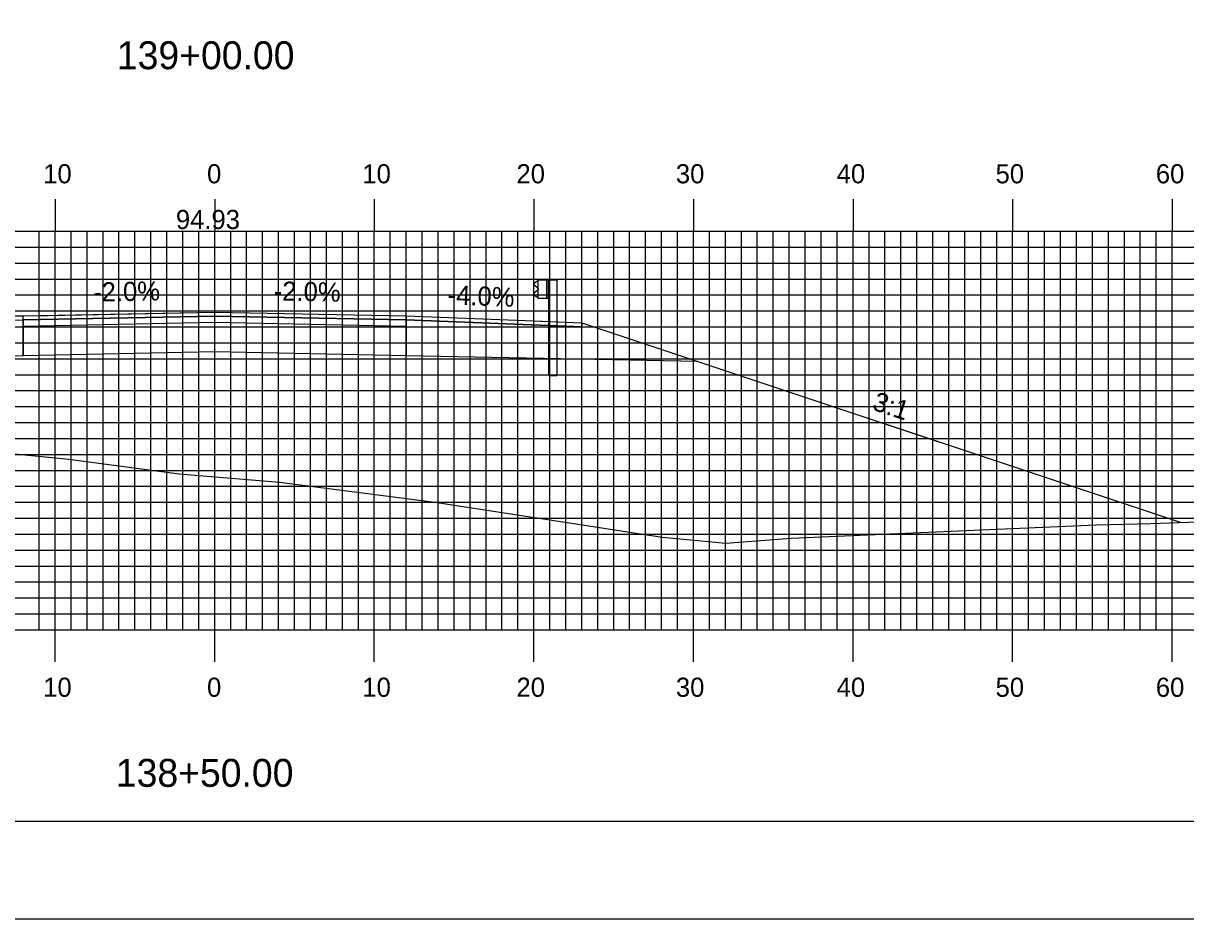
# Model space of a CAD drawing. Extents: x 1775957 to 1776301, y 442591 to 442811.
# Drawn here: x 1776111.2 to 1776184.1, y 442590.5 to 442646.7 of the extents above; entities that cross this region are included whole.
import ezdxf

# ---------------------------------------------------------------- set-up
doc = ezdxf.new("R2010")
doc.units = 0
for name, color, linetype in [('ANNOTATION', 7, 'Continuous'), ('BORDER', 7, 'Continuous'), ('D_Guardrail_Beam_Rt', 7, 'Continuous'), ('D_Roadway_Centerline', 7, 'Continuous'), ('D_Roadway_Centerline_Text', 7, 'Continuous'), ('D_Roadway_Edge_Shoulder', 7, 'Continuous'), ('D_Roadway_Edge_TW', 7, 'Continuous'), ('D_Roadway_Pavement', 7, 'Continuous'), ('D_Roadway_SlopeLines', 7, 'Continuous'), ('D_Roadway_SubGrade', 7, 'Continuous'), ('H_V ANNOTATION', 7, 'Continuous'), ('MAJOR', 7, 'Continuous'), ('MINOR', 7, 'Continuous'), ('PLOT BOUNDARY', 7, 'Continuous'), ('S_Roadway_Centerline', 7, 'Continuous')]:
    doc.layers.add(name, color=color, linetype=linetype)

msp = doc.modelspace()

# ---------------------------------------------------------------- linework, layer by layer
at = {"layer": 'BORDER'}
msp.add_lwpolyline([(1775973.624, 442596.665), (1776293.624, 442596.665), (1776293.624, 442806.665), (1775973.624, 442806.665)], close=True, dxfattribs=at)
at = {"layer": 'D_Guardrail_Beam_Rt'}
for p, q in [((1776143.405, 442630.513), (1776143.262, 442630.413)), ((1776143.495, 442630.534), (1776143.421, 442630.52)), ((1776143.495, 442630.618), (1776144.183, 442630.618)), ((1776143.495, 442629.451), (1776143.495, 442630.618)), ((1776144.016, 442630.618), (1776144.016, 442629.451)), ((1776144.12, 442630.618), (1776144.12, 442629.451)), ((1776144.183, 442630.618), (1776144.653, 442630.618)), ((1776144.183, 442630.618), (1776144.183, 442629.451)), ((1776144.653, 442630.618), (1776144.653, 442624.618)), ((1776143.262, 442630.27), (1776143.457, 442630.134)), ((1776143.457, 442629.935), (1776143.262, 442629.799)), ((1776143.491, 442630.069), (1776143.491, 442629.999)), ((1776143.262, 442629.655), (1776143.405, 442629.555)), ((1776143.421, 442629.549), (1776143.495, 442629.534)), ((1776144.183, 442629.451), (1776143.495, 442629.451)), ((1776144.162, 442624.618), (1776144.162, 442629.451)), ((1776144.162, 442624.618), (1776144.653, 442624.618))]:
    msp.add_line(p, q, dxfattribs=at)
for centre, major_axis, start_param, end_param in [((1776143.429, 442630.479), (-0.0417, 0), 4.907132, 5.323254), ((1776143.312, 442630.341), (-0.0877, 0), 5.323254, 7.243116), ((1776143.312, 442629.727), (-0.0877, 0), 5.323254, 7.243116), ((1776143.412, 442630.069), (0.0789, 0), 0, 0.959931), ((1776143.412, 442629.999), (0.0789, 0), 5.323254, 6.283185), ((1776143.429, 442629.589), (-0.0417, 0), 0.959931, 1.376053)]:
    msp.add_ellipse(centre, major_axis=major_axis, ratio=0.995501, start_param=start_param, end_param=end_param, dxfattribs=at)
at = {"layer": 'D_Roadway_Centerline'}
msp.add_lwpolyline([(1776076.998, 442623.12), (1776081.579, 442624.647), (1776081.581, 442624.648), (1776083.119, 442625.033), (1776084.245, 442625.314), (1776084.249, 442625.315), (1776093.581, 442627.648), (1776093.59, 442627.649), (1776111.225, 442628.354), (1776112.792, 442628.386), (1776123.225, 442628.594), (1776135.224, 442628.354), (1776143.224, 442628.034), (1776144.123, 442627.998), (1776146.224, 442627.914), (1776153.5, 442625.489), (1776153.501, 442625.488), (1776183.777, 442615.396)], dxfattribs=at)
at = {"layer": 'D_Roadway_Edge_Shoulder'}
for points in [[(1776111.225, 442628.354), (1776093.581, 442627.648), (1776093.581, 442627.398), (1776111.225, 442628.104)], [(1776135.224, 442628.354), (1776143.224, 442628.034), (1776143.224, 442628.034), (1776146.224, 442627.914), (1776146.224, 442627.664), (1776135.224, 442628.104)]]:
    msp.add_lwpolyline(points, close=True, dxfattribs=at)
at = {"layer": 'D_Roadway_Edge_TW'}
msp.add_lwpolyline([(1776111.225, 442628.104), (1776111.225, 442628.354), (1776123.225, 442628.594), (1776135.224, 442628.354), (1776135.224, 442628.104), (1776123.225, 442628.344)], close=True, dxfattribs=at)
at = {"layer": 'D_Roadway_Pavement'}
msp.add_lwpolyline([(1776111.225, 442627.687), (1776111.225, 442628.104), (1776123.225, 442628.344), (1776135.224, 442628.104), (1776135.224, 442627.687), (1776123.225, 442627.927)], close=True, dxfattribs=at)
at = {"layer": 'D_Roadway_SlopeLines'}
msp.add_lwpolyline([(1776146.224, 442627.914), (1776183.777, 442615.396)], dxfattribs=at)
at = {"layer": 'D_Roadway_SubGrade'}
for points in [[(1776111.225, 442625.854), (1776111.225, 442628.104), (1776123.225, 442628.344), (1776135.224, 442628.104), (1776135.224, 442625.854), (1776123.225, 442626.094)], [(1776111.225, 442625.854), (1776084.245, 442625.314), (1776093.581, 442627.648), (1776093.581, 442627.398), (1776111.225, 442628.104)], [(1776135.224, 442628.104), (1776146.224, 442627.664), (1776146.224, 442627.914), (1776153.501, 442625.488), (1776135.224, 442625.854)]]:
    msp.add_lwpolyline(points, close=True, dxfattribs=at)
at = {"layer": 'MAJOR'}
for p, q in [((1776113.224, 442635.669), (1776113.224, 442633.665)), ((1776123.224, 442635.669), (1776123.224, 442633.665)), ((1776133.224, 442635.669), (1776133.224, 442633.665)), ((1776143.224, 442635.669), (1776143.224, 442633.665)), ((1776153.224, 442635.669), (1776153.224, 442633.665)), ((1776163.224, 442635.669), (1776163.224, 442633.665)), ((1776173.224, 442635.669), (1776173.224, 442633.665)), ((1776183.224, 442635.669), (1776183.224, 442633.665)), ((1775983.224, 442633.665), (1776263.224, 442633.665)), ((1775983.224, 442633.665), (1776263.224, 442633.665)), ((1776113.224, 442608.665), (1776113.224, 442633.665)), ((1776123.224, 442608.665), (1776123.224, 442633.665)), ((1776133.224, 442608.665), (1776133.224, 442633.665)), ((1776143.224, 442608.665), (1776143.224, 442633.665)), ((1776153.224, 442608.665), (1776153.224, 442633.665)), ((1776163.224, 442608.665), (1776163.224, 442633.665)), ((1776173.224, 442608.665), (1776173.224, 442633.665)), ((1776183.224, 442608.665), (1776183.224, 442633.665)), ((1775983.224, 442628.665), (1776263.224, 442628.665)), ((1775983.224, 442623.665), (1776263.224, 442623.665)), ((1775983.224, 442618.665), (1776263.224, 442618.665)), ((1775983.224, 442613.665), (1776263.224, 442613.665)), ((1775983.224, 442608.665), (1776263.224, 442608.665)), ((1775983.224, 442608.665), (1776263.224, 442608.665)), ((1776113.224, 442606.661), (1776113.224, 442608.665)), ((1776123.224, 442606.661), (1776123.224, 442608.665)), ((1776133.224, 442606.661), (1776133.224, 442608.665)), ((1776143.224, 442606.661), (1776143.224, 442608.665)), ((1776153.224, 442606.661), (1776153.224, 442608.665)), ((1776163.224, 442606.661), (1776163.224, 442608.665)), ((1776173.224, 442606.661), (1776173.224, 442608.665)), ((1776183.224, 442606.661), (1776183.224, 442608.665))]:
    msp.add_line(p, q, dxfattribs=at)
at = {"layer": 'MINOR'}
for p, q in [((1776112.224, 442608.665), (1776112.224, 442633.665)), ((1776114.224, 442608.665), (1776114.224, 442633.665)), ((1776115.224, 442608.665), (1776115.224, 442633.665)), ((1776116.224, 442608.665), (1776116.224, 442633.665)), ((1776117.224, 442608.665), (1776117.224, 442633.665)), ((1776118.224, 442608.665), (1776118.224, 442633.665)), ((1776119.224, 442608.665), (1776119.224, 442633.665)), ((1776120.224, 442608.665), (1776120.224, 442633.665)), ((1776121.224, 442608.665), (1776121.224, 442633.665)), ((1776122.224, 442608.665), (1776122.224, 442633.665)), ((1776124.224, 442608.665), (1776124.224, 442633.665)), ((1776125.224, 442608.665), (1776125.224, 442633.665)), ((1776126.224, 442608.665), (1776126.224, 442633.665)), ((1776127.224, 442608.665), (1776127.224, 442633.665)), ((1776128.224, 442608.665), (1776128.224, 442633.665)), ((1776129.224, 442608.665), (1776129.224, 442633.665)), ((1776130.224, 442608.665), (1776130.224, 442633.665)), ((1776131.224, 442608.665), (1776131.224, 442633.665)), ((1776132.224, 442608.665), (1776132.224, 442633.665)), ((1776134.224, 442608.665), (1776134.224, 442633.665)), ((1776135.224, 442608.665), (1776135.224, 442633.665)), ((1776136.224, 442608.665), (1776136.224, 442633.665)), ((1776137.224, 442608.665), (1776137.224, 442633.665)), ((1776138.224, 442608.665), (1776138.224, 442633.665)), ((1776139.224, 442608.665), (1776139.224, 442633.665)), ((1776140.224, 442608.665), (1776140.224, 442633.665)), ((1776141.224, 442608.665), (1776141.224, 442633.665)), ((1776142.224, 442608.665), (1776142.224, 442633.665)), ((1776144.224, 442608.665), (1776144.224, 442633.665)), ((1776145.224, 442608.665), (1776145.224, 442633.665)), ((1776146.224, 442608.665), (1776146.224, 442633.665)), ((1776147.224, 442608.665), (1776147.224, 442633.665)), ((1776148.224, 442608.665), (1776148.224, 442633.665)), ((1776149.224, 442608.665), (1776149.224, 442633.665)), ((1776150.224, 442608.665), (1776150.224, 442633.665)), ((1776151.224, 442608.665), (1776151.224, 442633.665)), ((1776152.224, 442608.665), (1776152.224, 442633.665)), ((1776154.224, 442608.665), (1776154.224, 442633.665)), ((1776155.224, 442608.665), (1776155.224, 442633.665)), ((1776156.224, 442608.665), (1776156.224, 442633.665)), ((1776157.224, 442608.665), (1776157.224, 442633.665)), ((1776158.224, 442608.665), (1776158.224, 442633.665)), ((1776159.224, 442608.665), (1776159.224, 442633.665)), ((1776160.224, 442608.665), (1776160.224, 442633.665)), ((1776161.224, 442608.665), (1776161.224, 442633.665)), ((1776162.224, 442608.665), (1776162.224, 442633.665)), ((1776164.224, 442608.665), (1776164.224, 442633.665)), ((1776165.224, 442608.665), (1776165.224, 442633.665)), ((1776166.224, 442608.665), (1776166.224, 442633.665)), ((1776167.224, 442608.665), (1776167.224, 442633.665)), ((1776168.224, 442608.665), (1776168.224, 442633.665)), ((1776169.224, 442608.665), (1776169.224, 442633.665)), ((1776170.224, 442608.665), (1776170.224, 442633.665)), ((1776171.224, 442608.665), (1776171.224, 442633.665)), ((1776172.224, 442608.665), (1776172.224, 442633.665)), ((1776174.224, 442608.665), (1776174.224, 442633.665)), ((1776175.224, 442608.665), (1776175.224, 442633.665)), ((1776176.224, 442608.665), (1776176.224, 442633.665)), ((1776177.224, 442608.665), (1776177.224, 442633.665)), ((1776178.224, 442608.665), (1776178.224, 442633.665)), ((1776179.224, 442608.665), (1776179.224, 442633.665)), ((1776180.224, 442608.665), (1776180.224, 442633.665)), ((1776181.224, 442608.665), (1776181.224, 442633.665)), ((1776182.224, 442608.665), (1776182.224, 442633.665)), ((1775983.224, 442632.665), (1776263.224, 442632.665)), ((1775983.224, 442631.665), (1776263.224, 442631.665)), ((1775983.224, 442630.665), (1776263.224, 442630.665)), ((1775983.224, 442629.665), (1776263.224, 442629.665)), ((1775983.224, 442627.665), (1776263.224, 442627.665)), ((1775983.224, 442626.665), (1776263.224, 442626.665)), ((1775983.224, 442625.665), (1776263.224, 442625.665)), ((1775983.224, 442624.665), (1776263.224, 442624.665)), ((1775983.224, 442622.665), (1776263.224, 442622.665)), ((1775983.224, 442621.665), (1776263.224, 442621.665)), ((1775983.224, 442620.665), (1776263.224, 442620.665)), ((1775983.224, 442619.665), (1776263.224, 442619.665)), ((1775983.224, 442617.665), (1776263.224, 442617.665)), ((1775983.224, 442616.665), (1776263.224, 442616.665)), ((1775983.224, 442615.665), (1776263.224, 442615.665)), ((1775983.224, 442614.665), (1776263.224, 442614.665)), ((1775983.224, 442612.665), (1776263.224, 442612.665)), ((1775983.224, 442611.665), (1776263.224, 442611.665)), ((1775983.224, 442610.665), (1776263.224, 442610.665)), ((1775983.224, 442609.665), (1776263.224, 442609.665))]:
    msp.add_line(p, q, dxfattribs=at)
at = {"layer": 'PLOT BOUNDARY'}
msp.add_lwpolyline([(1775957.438, 442590.547), (1776297.438, 442590.547), (1776297.438, 442810.547), (1775957.438, 442810.547)], close=True, dxfattribs=at)
at = {"layer": 'S_Roadway_Centerline'}
msp.add_lwpolyline([(1776055.562, 442624.302), (1776068.536, 442623.626), (1776080.517, 442622.91), (1776085.78, 442622.198), (1776090.619, 442621.727), (1776097.486, 442620.784), (1776104.82, 442620.328), (1776109.603, 442619.798), (1776114.088, 442619.373), (1776121.002, 442618.447), (1776127.287, 442617.922), (1776137.026, 442616.667), (1776143.946, 442615.606), (1776151.265, 442614.477), (1776155.243, 442614.096), (1776159.346, 442614.409), (1776178.449, 442615.24), (1776181.881, 442615.329), (1776198.429, 442615.918)], dxfattribs=at)

# ---------------------------------------------------------------- texts
at = {"layer": 'ANNOTATION'}
for s, rotation, p in [('-2.0%', 1.14576, (1776115.615, 442629.242)), ('-2.0%', 358.85418, (1776126.911, 442629.321)), ('-4.0%', 357.70947, (1776137.798, 442629.084)), ('3:1', 341.56506, (1776164.37, 442622.489))]:
    msp.add_text(s, height=1.2, rotation=rotation, dxfattribs=at).set_placement(p)
at = {"layer": 'D_Roadway_Centerline'}
for s, p in [('C', (1776123.219, 442628.594)), ('L', (1776123.225, 442628.587))]:
    msp.add_text(s, height=0.0146, dxfattribs=at).set_placement(p)
at = {"layer": 'D_Roadway_Centerline_Text'}
msp.add_text('94.93', height=1.2, dxfattribs=at).set_placement((1776120.79, 442633.798))
at = {"layer": 'H_V ANNOTATION'}
for s, height, p in [('139+00.00', 1.75, (1776117.092, 442643.821)), ('10', 1.2, (1776112.475, 442636.665)), ('0', 1.2, (1776122.743, 442636.665)), ('10', 1.2, (1776132.475, 442636.665)), ('20', 1.2, (1776142.132, 442636.665)), ('30', 1.2, (1776152.122, 442636.665)), ('40', 1.2, (1776162.197, 442636.665)), ('50', 1.2, (1776172.154, 442636.665)), ('60', 1.2, (1776182.197, 442636.665)), ('10', 1.2, (1776112.475, 442604.465)), ('0', 1.2, (1776122.743, 442604.465)), ('10', 1.2, (1776132.475, 442604.465)), ('20', 1.2, (1776142.132, 442604.465)), ('30', 1.2, (1776152.122, 442604.465)), ('40', 1.2, (1776162.197, 442604.465)), ('50', 1.2, (1776172.154, 442604.465)), ('60', 1.2, (1776182.197, 442604.465)), ('138+50.00', 1.75, (1776117.029, 442598.821))]:
    msp.add_text(s, height=height, dxfattribs=at).set_placement(p)

doc.saveas('drawing.dxf')
